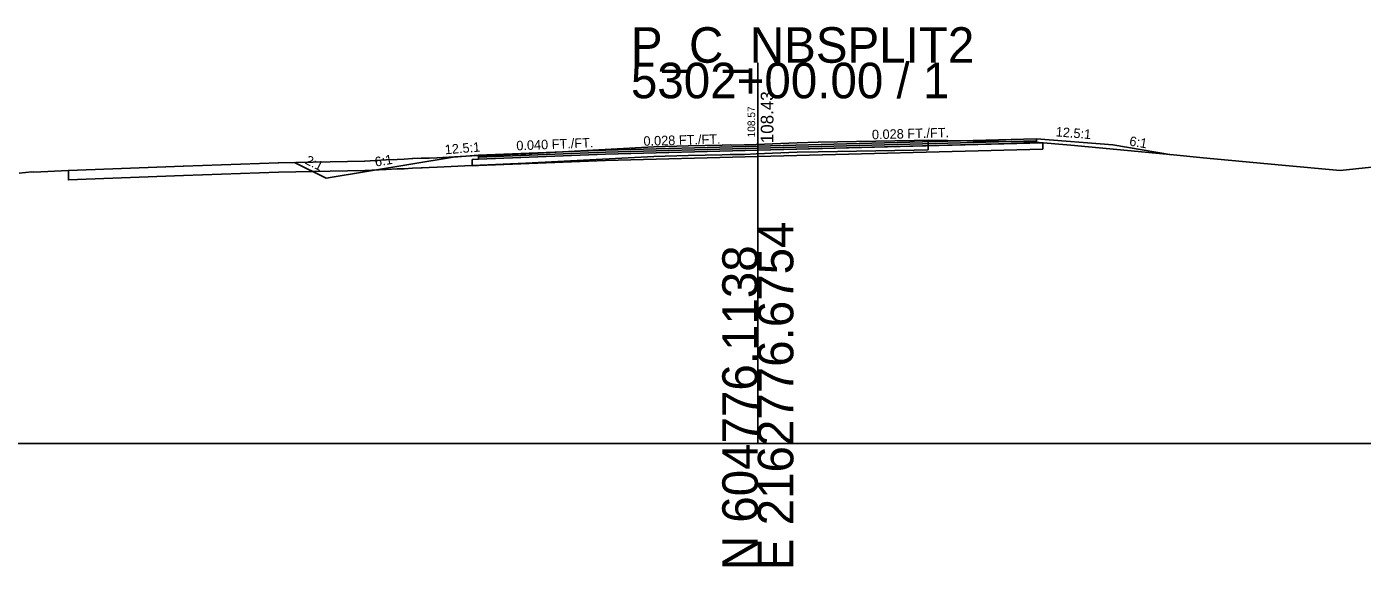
# Model space of a CAD drawing. Extents: x -26 to 1303, y -10 to 12038.
# Drawn here: x 92.4 to 197.6, y 11490.3 to 11532.8 of the extents above; entities that cross this region are included whole.
import ezdxf

# ---------------------------------------------------------------- set-up
doc = ezdxf.new("R2010")
doc.units = 0
for name, color, linetype in [('RD_GPK_XS_Cell', 7, 'Continuous'), ('RD_XS_Base', 7, 'Continuous'), ('RD_XS_ExGround', 7, 'Continuous'), ('RD_XS_ExPaveRet', 7, 'Continuous'), ('RD_XS_Greenside', 7, 'Continuous'), ('RD_XS_Pave', 7, 'Continuous'), ('RD_XS_PaveOvlay_CP', 7, 'Continuous'), ('RD_XS_TieSlope', 7, 'Continuous'), ('RD_XS_TX_Elev_EX', 7, 'Continuous'), ('RD_XS_TX_Elev_PR', 7, 'Continuous'), ('RD_XS_TX_ShdSlope', 7, 'Continuous'), ('RD_XS_TX_Slope', 7, 'Continuous')]:
    doc.layers.add(name, color=color, linetype=linetype)

msp = doc.modelspace()

# ---------------------------------------------------------------- linework, layer by layer
at = {"layer": 'RD_GPK_XS_Cell'}
for p, q in [((150, 11500), (150, 11530)), ((0, 11500), (150, 11500)), ((150, 11500), (300, 11500))]:
    msp.add_line(p, q, dxfattribs=at)
at = {"layer": 'RD_XS_Base'}
for p, q in [((150, 11523.11), (172.46, 11523.69)), ((171.96, 11523.68), (171.96, 11523.68)), ((172.46, 11523.69), (172.46, 11523.19)), ((172.46, 11523.66), (172.46, 11523.66)), ((138, 11522.8), (128, 11522.4)), ((150, 11523.11), (138, 11522.8)), ((138, 11522.8), (138, 11522.8)), ((138, 11522.3), (150, 11522.61)), ((150, 11522.61), (150, 11523.27)), ((150, 11523.27), (150, 11523.27)), ((150, 11523.27), (150, 11523.27)), ((150, 11523.27), (150, 11523.11)), ((172.46, 11523.19), (150, 11522.61)), ((150, 11523.11), (150, 11523.11)), ((150, 11522.61), (150, 11523.11)), ((150, 11523.11), (150, 11523.11)), ((150, 11523.11), (150, 11523.11)), ((150, 11522.61), (150, 11522.61)), ((128, 11522.4), (127.5, 11522.38)), ((127.5, 11522.38), (127.5, 11522.38)), ((127.5, 11522.38), (127.5, 11521.88)), ((127.5, 11521.88), (128, 11521.9)), ((128, 11522.4), (128, 11522.4)), ((128, 11521.9), (138, 11522.3)), ((128, 11521.9), (128, 11521.9)), ((138, 11522.3), (138, 11522.3))]:
    msp.add_line(p, q, dxfattribs=at)
at = {"layer": 'RD_XS_ExGround'}
msp.add_lwpolyline([(91.82, 11521.29), (92.8, 11521.39), (92.97, 11521.37), (95.69, 11521.51), (104.75, 11521.86), (112.23, 11522.12), (119.03, 11522.25), (120.71, 11522.34), (121.59, 11522.38), (122.14, 11522.4), (122.8, 11522.44), (123.47, 11522.47), (123.56, 11522.47), (124.1, 11522.48), (124.73, 11522.51), (127.48, 11522.65), (128.74, 11522.7), (131.72, 11522.83), (141.81, 11523.37), (144.52, 11523.44), (147.19, 11523.5), (147.83, 11523.52), (147.96, 11523.51), (148.95, 11523.53), (149.88, 11523.56), (153.11, 11523.69), (154.76, 11523.73), (162.33, 11523.86), (163.41, 11523.89), (171.06, 11523.76), (171.84, 11523.73), (174.66, 11523.5), (182.74, 11522.73), (185.09, 11522.51), (191.28, 11521.92), (195.88, 11521.51), (198.34, 11521.77)], dxfattribs=at)
at = {"layer": 'RD_XS_ExPaveRet'}
for points in [[(163.41, 11523.89), (163.41, 11523.89), (163.41, 11523.14), (163.41, 11523.14), (162.33, 11523.11), (162.33, 11523.11), (154.76, 11522.98), (154.76, 11522.98), (153.11, 11522.94), (153.11, 11522.94), (149.88, 11522.81), (149.88, 11522.81), (148.95, 11522.78), (148.95, 11522.78), (147.96, 11522.76), (147.96, 11522.76), (147.96, 11522.76), (147.83, 11522.77), (147.19, 11522.75), (147.19, 11522.75), (144.52, 11522.69), (144.52, 11522.69), (141.81, 11522.62), (141.81, 11522.62), (131.72, 11522.08), (131.72, 11522.08), (128.74, 11521.95), (127.48, 11521.9), (124.73, 11521.76), (124.73, 11521.76), (124.1, 11521.73), (124.1, 11521.73), (123.56, 11521.72), (123.47, 11521.72), (123.47, 11521.72), (122.8, 11521.69), (122.8, 11521.69), (122.14, 11521.65), (122.14, 11521.65), (121.59, 11521.63), (120.71, 11521.59), (120.71, 11521.59), (119.03, 11521.5), (119.03, 11521.5), (119.03, 11521.5), (112.23, 11521.37), (112.23, 11521.37), (112.23, 11521.37), (104.75, 11521.11), (104.75, 11521.11), (95.69, 11520.76), (95.69, 11520.76), (95.69, 11521.51), (95.69, 11521.51), (95.69, 11521.51), (104.75, 11521.86), (104.75, 11521.86), (112.23, 11522.12), (112.23, 11522.12), (112.23, 11522.12), (119.03, 11522.25), (119.03, 11522.25), (119.03, 11522.25), (120.71, 11522.34), (120.71, 11522.34), (121.59, 11522.38), (122.14, 11522.4), (122.14, 11522.4), (122.8, 11522.44), (122.8, 11522.44), (123.47, 11522.47), (123.47, 11522.47), (123.56, 11522.47), (124.1, 11522.48), (124.1, 11522.48), (124.73, 11522.51), (124.73, 11522.51), (127.48, 11522.65), (128.74, 11522.7), (131.72, 11522.83), (131.72, 11522.83), (141.81, 11523.37), (141.81, 11523.37), (144.52, 11523.44), (144.52, 11523.44), (147.19, 11523.5), (147.19, 11523.5), (147.83, 11523.52), (147.96, 11523.51), (147.96, 11523.51), (147.96, 11523.51), (148.95, 11523.53), (148.95, 11523.53), (149.88, 11523.56), (149.88, 11523.56), (153.11, 11523.69), (153.11, 11523.69), (154.76, 11523.73), (154.76, 11523.73), (162.33, 11523.86), (162.33, 11523.86), (163.41, 11523.89), (163.41, 11523.89)], [(162.33, 11523.86), (154.76, 11523.73), (153.11, 11523.69), (149.88, 11523.56), (148.95, 11523.53), (147.96, 11523.51), (147.83, 11523.52), (147.19, 11523.5), (144.52, 11523.44), (141.81, 11523.37), (131.72, 11522.83), (128.74, 11522.7), (127.48, 11522.65), (124.73, 11522.51), (124.1, 11522.48), (123.56, 11522.47), (123.47, 11522.47), (122.8, 11522.44), (122.14, 11522.4), (121.59, 11522.38), (120.71, 11522.34), (119.03, 11522.25), (112.23, 11522.12), (104.75, 11521.86), (95.69, 11521.51), (95.69, 11521.51), (95.69, 11520.76), (95.69, 11520.76), (104.75, 11521.11), (112.23, 11521.37), (119.03, 11521.5), (120.71, 11521.59), (121.59, 11521.63), (122.14, 11521.65), (122.8, 11521.69), (123.47, 11521.72), (123.56, 11521.72), (124.1, 11521.73), (124.73, 11521.76), (127.48, 11521.9), (128.74, 11521.95), (131.72, 11522.08), (141.81, 11522.62), (144.52, 11522.69), (147.19, 11522.75), (147.83, 11522.77), (147.96, 11522.76), (148.95, 11522.78), (149.88, 11522.81), (153.11, 11522.94), (154.76, 11522.98), (162.33, 11523.11), (163.41, 11523.14), (163.41, 11523.89), (162.33, 11523.86)]]:
    msp.add_lwpolyline(points, dxfattribs=at)
at = {"layer": 'RD_XS_Greenside'}
for p, q in [((126, 11522.56), (116, 11520.89)), ((177.96, 11523.52), (182.59, 11522.75)), ((116, 11520.89), (113.5, 11522.14))]:
    msp.add_line(p, q, dxfattribs=at)
at = {"layer": 'RD_XS_Pave'}
for p, q in [((171.96, 11524), (150, 11523.43)), ((171.96, 11523.84), (150, 11523.27)), ((150, 11523.27), (171.96, 11523.84)), ((150, 11523.11), (171.96, 11523.68)), ((171.96, 11523.84), (171.96, 11524)), ((171.96, 11524), (171.96, 11524)), ((171.96, 11523.68), (171.96, 11523.84)), ((171.96, 11523.84), (171.96, 11523.84)), ((138, 11523.12), (128, 11522.72)), ((128, 11522.56), (138, 11522.96)), ((138, 11522.96), (128, 11522.56)), ((128, 11522.4), (138, 11522.8)), ((128, 11522.72), (128, 11522.72)), ((128, 11522.72), (128, 11522.56)), ((128, 11522.56), (128, 11522.56)), ((128, 11522.56), (128, 11522.4)), ((150, 11523.43), (138, 11523.12)), ((138, 11522.96), (150, 11523.27)), ((150, 11523.27), (138, 11522.96)), ((138, 11523.12), (138, 11523.12)), ((138, 11522.8), (150, 11523.11)), ((138, 11522.96), (138, 11522.96)), ((138, 11522.96), (138, 11522.96)), ((138, 11522.8), (138, 11522.8)), ((150, 11523.43), (150, 11523.43)), ((150, 11523.27), (150, 11523.27)), ((150, 11523.27), (150, 11523.27)), ((150, 11523.27), (150, 11523.11)), ((150, 11523.27), (150, 11523.27)), ((150, 11523.11), (150, 11523.27)), ((150, 11523.27), (150, 11523.27)), ((150, 11523.27), (150, 11523.27)), ((150, 11523.11), (150, 11523.11)), ((150, 11523.11), (150, 11523.11))]:
    msp.add_line(p, q, dxfattribs=at)
at = {"layer": 'RD_XS_PaveOvlay_CP'}
for p, q in [((171.96, 11524), (150, 11523.43)), ((138, 11523.12), (128, 11522.72)), ((150, 11523.43), (138, 11523.12)), ((138, 11523.12), (138, 11523.12)), ((150, 11523.43), (150, 11523.43))]:
    msp.add_line(p, q, dxfattribs=at)
at = {"layer": 'RD_XS_TieSlope'}
for p, q in [((171.96, 11524), (177.96, 11523.52)), ((128, 11522.72), (126, 11522.56))]:
    msp.add_line(p, q, dxfattribs=at)

# ---------------------------------------------------------------- texts
at = {"layer": 'RD_GPK_XS_Cell'}
for s, p in [('P_C_NBSPLIT2', (140, 11530)), ('5302+00.00 / 1', (140, 11527.2))]:
    msp.add_text(s, height=2.8, dxfattribs=at).set_placement(p)
for s, p in [('E 2162776.6754', (152.8, 11490)), ('N 604776.1138', (150, 11490))]:
    msp.add_text(s, height=2.8, rotation=90, dxfattribs=at).set_placement(p)
at = {"layer": 'RD_XS_TX_Elev_EX'}
msp.add_text('108.57', height=0.6, rotation=90, dxfattribs=at).set_placement((149.79, 11524.11))
at = {"layer": 'RD_XS_TX_Elev_PR'}
msp.add_text('108.43', height=1, rotation=90, dxfattribs=at).set_placement((151.23, 11523.66))
at = {"layer": 'RD_XS_TX_ShdSlope'}
for rotation, p in [(355.4261, (173.45, 11524.2)), (4.5739, (125.37, 11522.78))]:
    msp.add_text('12.5:1', height=0.75, rotation=rotation, dxfattribs=at).set_placement(p)
at = {"layer": 'RD_XS_TX_Slope'}
for s, rotation, p in [('0.028 FT./FT.', 1.6039, (159, 11523.96)), ('0.040 FT./FT.', 2.2906, (130.99, 11523.09)), ('0.028 FT./FT.', 1.6039, (141, 11523.45)), ('6:1', 350.5377, (179.23, 11523.48)), ('2:1', 333.4349, (114.27, 11522.07)), ('6:1', 9.4642, (119.89, 11521.81))]:
    msp.add_text(s, height=0.75, rotation=rotation, dxfattribs=at).set_placement(p)

doc.saveas('drawing.dxf')
